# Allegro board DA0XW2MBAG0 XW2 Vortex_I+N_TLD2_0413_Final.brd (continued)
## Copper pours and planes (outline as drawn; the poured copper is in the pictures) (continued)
+SMDDR_VREF_CHB_DIMM_R on BOTTOM (solid shape): 156.67,24.83 156.67,24.55 157,24.22 157,23.64 156.88,23.51 155.94,23.51 155.63,23.81 155.3,23.81 155.23,23.89 155.23,25.29 155.3,25.36 156.15,25.36
+TBT_SVR_IND on BOTTOM (solid shape): outline of 279 points within 349.54,112.23 356.27,117.64
+VAC on TOP (solid shape): 349.54,144.77 349.54,142.92 350.15,142.31 350.15,140.32 349.89,140.07 347.48,140.07 347.22,140.32 347.22,144.26 347.35,144.39 347.99,144.39 348.62,145.02 349.28,145.02
+VAC on BOTTOM (solid shape): outline of 356 points within 343.57,139.79 359.24,148.15
+VAC on IN1 (solid shape): outline of 554 points within 346.84,112.8 350.36,120.87
+VAC on IN3 (solid shape): outline of 187 points within 347.25,41.59 352.58,44.92
+VREFCA_CHA_DIMM on BOTTOM (solid shape): 138.62,27.67 138.82,27.47 138.82,26.58 138.75,26.51 134.35,26.51 134.25,26.54 134.14,26.54 133.87,26.54 133.77,26.63 133.66,26.63 133.61,26.68 133.61,27.5 133.76,27.65 138.27,27.65 138.31,27.68 138.61,27.68
+VREFCA_CHB_DIMM on BOTTOM (solid shape): 155.28,27.5 155.28,27.07 155.78,26.56 155.78,25.72 155.69,25.62 155.12,25.62 155.1,25.62 154.9,25.41 154.9,23.33 154.64,23.08 150.83,23.08 150.72,23.2 150.7,23.2 150.7,23.92 150.81,24.02 153.6,24.02 154.08,24.5 154.08,26.08 154.57,26.56 154.57,27.65 154.62,27.7 155.07,27.7
BATT+ on BOTTOM (solid shape): 212.24,5.78 212.37,5.78 212.39,5.76 213.99,5.76 214.01,5.78 214.33,5.78 214.34,5.76 215.95,5.76 215.96,5.78 216.31,5.78 216.33,5.76 217.93,5.76 217.94,5.78 218.7,5.78 218.82,5.66 218.82,5.39 218.17,4.73 218.17,3.67 217.58,3.09 217.58,2.08 217.57,2.05 217.53,2.03 213.32,2.03 213.28,2.05 213.27,2.08 213.27,3.16 211.5,4.93 211.49,4.93 211.36,5.06 211.36,5.86 211.5,6 212.02,6
BQPHASE on BOTTOM (solid shape): 241.6,25.89 241.6,24.86 241.92,24.55 243.41,24.55 243.64,24.33 243.64,21.2 243.36,20.92 236,20.92 235.62,20.54 235.62,20.21 235.63,20.2 235.63,19.56 235.9,19.29 236.58,19.29 236.68,19.19 236.68,18.4 236.63,18.35 235.77,18.35 235.59,18.18 235.59,15.92 235.34,15.66 229.51,15.66 229,16.17 229,21.2 229.71,21.91 232.29,21.91 236.4,26.02 241.47,26.02
BQVCC on BOTTOM (solid shape): 250,15.8 250,14.96 249.23,14.19 247.74,14.19 247.67,14.26 247.67,14.99 247.99,15.3 248,15.3 248.21,15.42 248.32,15.62 248.32,15.64 248.64,15.95 249.85,15.95
CORE_PLLVDD on TOP (solid shape): 209.21,105.12 209.58,105.12 209.71,104.99 209.71,104.48 209.46,104.23 209.46,104.2 209.45,104.2 209.45,103.59 209.32,103.46 206.66,103.46 206.16,103.96 206.16,105 206.29,105.13 209.2,105.13
CORE_PLLVDD on BOTTOM (solid shape): 232.25,126.34 232.25,122.07 232.67,121.65 232.67,121.63 232.97,121.34 233,121.31 233.04,121.28 233.21,121.11 233.21,120.41 233.09,120.29 230.88,120.29 230.37,120.8 230.37,126.17 230.82,126.62 231.96,126.62
CORE_PLLVDD on IN1 (solid shape): outline of 975 points within 206.14,103.34 221.87,119.98
CTRL_1P0 on BOTTOM (solid shape): 20.26,125.44 20.43,125.37 20.61,125.39 20.64,125.39 20.67,125.38 21.62,124.42 22.29,124.42 22.33,124.41 22.34,124.37 22.34,124.34 23.34,124.34 23.35,124.35 23.4,124.3 23.4,124.19 23.39,124.16 23.35,124.14 22.34,124.14 22.34,124.11 22.33,124.07 22.29,124.06 22.23,124.06 22.21,124.04 21.75,124.04 21.73,124.03 21.71,124.02 21.7,124.02 21.36,123.92 21.26,123.59 21.26,123.56 21.25,123.54 21.11,123.41 17.69,123.41 17.43,123.66 17.43,125.19 17.69,125.44
FBA_VREFC on TOP (solid shape): 228.11,144.12 228.11,140.55 227.93,140.37 227.56,140.37 227.37,140.55 227.37,141.85 227.21,142.02 226.76,142.02 226.58,142.2 226.58,142.61 226.7,142.73 227.01,142.73 227.42,143.14 227.42,144.05 227.57,144.2 228.03,144.2
FBVDDQ_MEM on TOP (solid shape): 228.22,142.16 228.29,142.25 228.4,142.23 228.46,142.17 228.75,142.17 228.88,142.04 228.88,141.97 229.22,141.63 229.23,141.61 229.41,141.38 229.71,141.36 230.03,141.36 230.16,141.23 230.16,140.88 229.97,140.69 229.34,140.69 229,141.03 228.93,141.03 228.9,141.04 228.81,141.18 228.68,141.23 228.4,141.23 228.35,141.22 228.26,141.24 228.22,141.32
FBVDDQ_MEM on TOP (solid shape): outline of 28355 points within 193.5,95.65 253.5,151.88
FBVDDQ_MEM on BOTTOM (solid shape): 225.78,141.42 225.78,141.29 225.66,141.16 225.48,141.16 224.56,142.08 224.56,142.2 224.72,142.36 224.84,142.36
FBVDDQ_MEM on BOTTOM (solid shape): 251.38,110.21 251.38,109.94 250.59,109.15 250.47,109.15 250.36,109.26 250.36,110.16 250.57,110.38 251.21,110.38
FBVDDQ_MEM on BOTTOM (solid shape): 204.09,141.54 204.13,141.5 204.18,141.46 205.4,140.24 205.4,140.05 205.27,139.93 205.12,139.93 203.78,141.27 203.78,141.44 203.94,141.6 204.04,141.6
FBVDDQ_MEM on BOTTOM (solid shape): 243.43,108.74 243.52,108.65 243.62,108.6 244.34,107.88 244.34,107.7 244.19,107.55 244.01,107.55 243.13,108.44 243.13,108.61 243.25,108.74
FBVDDQ_MEM on BOTTOM (solid shape): 224.31,141.29 224.36,141.29 224.86,140.79 224.92,140.71 225,140.64 225,140.48 224.87,140.35 224.69,140.35 223.89,141.16 223.85,141.21 223.8,141.26 223.8,141.42 223.92,141.53 224.07,141.53
FBVDDQ_MEM on BOTTOM (solid shape): 243.39,107.21 243.45,107.08 243.56,106.98 243.56,106.91 243.38,106.74 243.2,106.74 242.46,107.48 242.42,107.55 242.36,107.61 242.36,107.78 242.52,107.93 242.67,107.93
FBVDDQ_MEM on BOTTOM (solid shape): 243.51,110.14 243.73,110.14 243.84,110.04 243.84,109.45 243.67,109.29 243.61,109.28 243.12,109.28 242.95,109.32 242.78,109.28 242.34,109.28 242.34,109.94 242.55,110.15 243.51,110.15
FBVDDQ_MEM on BOTTOM (solid shape): 198.63,141.34 198.63,141.24 197.93,140.54 197.73,140.44 197.63,140.24 197.23,139.84 197.08,139.84 197,139.92 196.98,139.95 196.93,140 196.93,140.23 197.18,140.48 197.22,140.48 198.28,141.54 198.43,141.54
FBVDDQ_MEM on BOTTOM (solid shape): 204.9,142.33 205.02,142.23 205.16,142.2 205.32,142.04 205.38,141.95 205.47,141.89 205.69,141.67 207.25,141.67 207.31,141.67 207.37,141.67 207.47,141.67 207.67,141.47 207.67,141.16 207.54,141.04 207.06,141.04 206.91,141.19 205.38,141.19 204.72,141.85 204.67,141.95 204.6,142.03 204.6,142.2 204.72,142.33
FBVDDQ_MEM on BOTTOM (solid shape): 247.9,130.77 247.9,129.6 247.57,129.27 247.57,128.28 247.75,128.1 247.75,127.69 247.62,127.57 247.34,127.57 247.19,127.72 247.12,127.72 247.1,127.73 246.83,127.76 246.62,127.59 246.53,127.54 246.44,127.59 246.36,127.69 246.25,127.75 246.24,127.75 245.87,128.12 245.87,128.99 245.59,129.27 245.59,130.79 245.64,130.84 247.82,130.84
FBVDDQ_MEM on BOTTOM (solid shape): 216.06,141.57 216.07,141.57 216.14,141.49 216.23,141.43 216.24,141.42 216.26,141.4 216.26,141.35 216.25,141.32 216.23,141.3 216,140.97 216.23,140.64 216.25,140.62 216.26,140.59 216.26,140.53 216.08,140.35 215.55,140.35 215.53,140.36 215.41,140.36 215.17,140.6 215.17,141.93 215.27,142.03 215.6,142.03
FBVDDQ_MEM on BOTTOM (solid shape): 240.96,126.53 241.03,126.39 241.14,126.28 241.14,126.14 240.92,125.92 240.92,125.81 240.98,125.75 241.08,125.56 241.26,125.47 241.78,124.95 241.83,124.82 241.93,124.72 241.93,124.59 241.78,124.44 241.58,124.44 240.85,125.17 240.78,125.27 240.68,125.34 240.28,125.74 240.28,125.97 240.43,126.12 240.43,126.37 240.26,126.55 240.26,126.68 240.48,126.91 240.59,126.91
FBVDDQ_MEM on BOTTOM (solid shape): 223.88,140.2 223.88,140.1 223.65,139.87 223.65,139.58 224.1,139.13 224.3,139 224.54,139.03 224.56,139.03 224.67,139.13 224.82,139.13 224.95,139 224.95,138.55 224.87,138.47 224.62,138.47 224.46,138.32 224.32,138.32 223.39,139.24 223.03,139.24 222.89,139.11 222.89,138.68 223.37,138.21 223.37,138.09 223.12,137.84 222.76,137.84 222.56,138.04 222.56,140.07 222.7,140.21 222.83,140.21 222.84,140.22 223.24,140.22 223.34,140.32 223.38,140.35 223.41,140.39 223.47,140.45 223.63,140.45
FBVDDQ_MEM on BOTTOM (solid shape): 243.52,101.41 243.55,101.33 243.51,101.26 243.5,101.25 243.42,101.17 243.37,101.07 243.37,101.06 242.76,100.45 242.7,100.41 242.65,100.35 242.63,100.34 242.61,100.33 242.48,100.33 242.46,100.34 242.44,100.35 242.39,100.4 242.33,100.44 242.29,100.49 242.29,100.59 242.29,100.62 242.31,100.63 242.37,100.68 242.42,100.73 242.45,100.78 242.48,100.85 243.2,101.58 243.35,101.58
FBVDDQ_MEM on BOTTOM (solid shape): 217.76,142.22 217.76,141.91 217.46,141.6 217.39,141.15 217.84,141.24 218.14,141.54 218.47,141.54 218.57,141.44 218.57,141.24 218.51,141.18 218.46,141.1 217.83,140.47 217.75,140.42 217.69,140.35 217.5,140.35 217.46,140.39 217.43,140.43 217.4,140.46 216.59,141.27 216.59,141.44 216.84,141.7 216.84,141.85 216.88,141.89 216.98,141.95 217.04,142.05 217.33,142.33 217.66,142.33
FBVDDQ_MEM on BOTTOM (solid shape): 239.57,99.04 239.57,98.76 239.39,98.58 239.39,98.11 239.52,97.97 239.53,97.97 239.58,97.92 240.2,97.92 240.48,98.2 240.48,98.73 240.79,99.04 241.09,99.04 241.25,98.89 241.25,96.36 241.07,96.18 240.08,96.18 240.04,96.22 238.58,96.22 238.44,96.08 238.44,95.37 237.93,94.86 237.93,94.22 237.92,94.17 237.92,93.69 237.8,93.56 237.27,93.56 237.14,93.69 237.14,97.3 237.88,98.03 237.9,98.03 238.15,98.14 238.25,98.38 238.25,98.4 238.49,98.64 238.51,98.66 238.53,98.66 238.58,98.66 238.64,98.68 238.81,98.68 239.28,99.15 239.46,99.15
FBVDDQ_MEM on BOTTOM (solid shape): 244.32,100.56 244.32,100.45 244.31,100.43 244.3,100.41 244.23,100.33 244.18,100.23 244.18,100.22 243.64,99.69 243.63,99.68 243.56,99.65 243.49,99.6 243.49,99.59 243.42,99.51 243.39,99.48 243.39,99.13 243.52,99 243.52,99 243.52,98.85 243.26,98.59 243.26,98.06 243.14,97.93 242.44,97.93 242.31,98.06 242.31,98.96 242.47,99.12 242.48,99.13 242.5,99.15 242.5,99.28 243.02,99.79 243.08,99.82 243.2,99.91 243.27,100.04 243.28,100.05 243.87,100.65 243.91,100.67 243.97,100.71 243.99,100.72 244.17,100.72
FBVDDQ_MEM on BOTTOM (solid shape): 241.91,102.21 241.91,102.02 241.84,101.94 241.79,101.85 241.78,101.83 241.77,101.76 241.77,101.72 241.75,101.65 241.69,101.62 241.52,101.53 241.45,101.36 241.45,101.34 241.42,101.31 241.4,101.29 241.38,101.29 241.01,101.1 241.07,100.69 241.14,100.62 241.14,100.51 241,100.37 240.92,100.37 240.69,100.6 240.55,100.6 240.26,100.89 240.26,101.02 240.63,101.4 240.64,101.4 240.78,101.49 240.87,101.62 240.87,101.64 241.55,102.32 241.8,102.32
FBVDDQ_MEM on BOTTOM (solid shape): outline of 260 points within 205.95,103.98 222.57,120.87
FBVDDQ_MEM on BOTTOM (solid shape): outline of 574 points within 245.08,95.69 255.29,108.68
FBVDDQ_MEM on BOTTOM (solid shape): outline of 404 points within 245.08,106.25 252.96,125.64
FBVDDQ_MEM on BOTTOM (solid shape): outline of 1473 points within 191.93,125.23 247.55,151.02
FBVDDQ_MEM on IN3 (solid shape): outline of 16488 points within 193.91,97.07 252.86,150.83
FBVDDQ_MEM on IN4 (solid shape): outline of 3922 points within 194.56,137.4 227.84,151.95
FBVDDQ_VIN on TOP (solid shape): 238.92,154.29 238.92,150.66 238.79,150.54 237.32,150.54 236.76,151.09 236.76,153.65 237.5,154.4 238.82,154.4
FBVDDQ_VIN on BOTTOM (solid shape): 239.05,154.24 239.05,150.37 238.92,150.24 238.92,147.19 238.91,147.16 238.9,147.15 238.87,147.14 238.51,147.14 238.3,146.93 238.3,146.61 238.29,146.6 238.28,146.57 238.27,146.54 238.24,146.52 238.22,146.5 238.18,146.5 238.15,146.5 238.12,146.5 238.09,146.52 238.07,146.54 238.05,146.57 238.04,146.6 238.04,146.61 238.04,146.93 237.83,147.14 237.6,147.15 237.59,147.16 237.58,147.19 237.58,150.08 237.54,150.12 238.04,150.12 238.04,150.73 237.8,150.73 237.8,150.12 237.54,150.12 237.54,150.12 237.54,150.73 237.01,151.25 237.01,151.96 236.84,152.14 232.18,152.14 231.98,152.34 231.98,153.27 232.19,153.49 236.74,153.49 237.65,154.4 238.89,154.4
G5719_LX on TOP (solid shape): 200.09,86.16 200.11,86.16 200.26,86.03 200.41,85.98 200.47,85.98 200.49,85.98 200.51,85.97 200.57,85.91 200.57,83.88 201.2,83.24 201.2,81.97 201.07,81.85 199.96,81.85 199.93,81.88 199.93,82.13 199.6,82.46 199.6,83.01 199.3,83.31 199.3,83.33 199.16,83.54 198.93,83.61 198.86,83.61 198.79,83.59 198.7,83.61 198.66,83.69 198.66,84.05 198.68,84.08 198.69,84.08 198.9,84.42 198.69,84.75 198.67,84.77 198.66,84.8 198.66,84.89 198.67,84.92 198.69,84.94 198.89,85.21 198.8,85.53 198.79,85.53 198.77,85.57 198.77,85.83 198.71,85.89 198.7,85.93 198.71,85.96 198.91,86.16
G5719_VIN on TOP (solid shape): 201.2,80.32 201.2,79.05 201.07,78.93 197.52,78.93 197.28,79.17 197.29,79.17 197.29,80.21 197.26,80.23 197.26,80.32 197.39,80.45 198.25,80.45 198.53,80.74 200.79,80.74
IO_VDD on BOTTOM (solid shape): 262.85,10.07 262.85,9.15 262.87,9.12 262.87,9.1 262.87,8.9 262.36,8.4 261.63,8.4 261.58,8.35 261.58,7.36 261.55,7.33 260.79,7.33 260.76,7.36 260.76,9.59 260.84,9.67 261.35,9.67 261.86,10.17 262.74,10.17
L_SPK+ on TOP (solid shape): 219.44,156.75 219.52,156.75 219.53,156.75 219.55,156.74 219.81,156.49 219.83,156.42 219.83,155.56 219.72,155.45 216.3,155.45 216.12,155.63 216.12,156.49 216.39,156.77 219.36,156.77
L_SPK+_R on TOP (solid shape): 217.22,154.99 217.23,154.98 217.23,154.96 217.23,154.26 217.03,154.05 216.65,154.05 215.84,153.24 215.84,153.02 215.52,152.7 214.39,152.7 214.26,152.83 214.26,153.28 214.43,153.44 214.72,153.44 215.01,153.74 215.01,153.87 215.02,153.87 215.02,154.39 215.74,155.12 217.09,155.12
L_SPK+_R on BOTTOM (solid shape): 214.71,154.6 215.35,154.6 216.06,153.89 216.06,152.62 215.81,152.36 214.43,152.36 214.2,152.58 214.2,153.43 213.72,153.91 213.72,155.01 213.77,155.06 214.26,155.06
L_SPK- on TOP (solid shape): 220.63,153.63 220.63,153.25 220.5,153.13 220.31,153.13 219.78,152.6 216.46,152.6 216.32,152.74 216.32,153.5 216.61,153.8 220.47,153.8
L_SPK-_R on TOP (solid shape): 214.06,153.16 214.06,152.69 214.48,152.27 217.21,152.27 217.42,152.05 217.42,151.32 217.35,151.24 213.48,151.24 213.2,151.52 213.2,153.21 213.39,153.4 213.82,153.4
L_SPK-_R on BOTTOM (solid shape): 213.42,155.03 213.42,153.96 214.03,153.35 214.03,152.62 214.28,152.36 214.28,151.6 213.9,151.22 213.27,151.22 213.14,151.35 213.14,153.18 212.91,153.41 212.91,155.06 212.93,155.08 213.37,155.08
NB679A_SW on BOTTOM (solid shape): 199.21,38.44 199.88,38.44 199.93,38.39 199.93,38.29 199.85,38.22 199.55,38.22 199.37,38.04 199.37,37.61 199.24,37.48 198.46,37.48 197.82,36.84 197.06,36.84 196.63,36.41 196.63,35.4 196.5,35.27 193.07,35.27 192.79,35.55 192.79,38.09 193.15,38.44 198.5,38.44
NB680A_BST on BOTTOM (solid shape): 220.02,43.35 220.02,42.38 219.92,42.28 219.56,42.28 219.44,42.41 219.44,42.86 219.31,42.99 219.03,42.99 218.93,43.09 218.93,43.47 218.98,43.52 219.84,43.52
NB680A_SW on BOTTOM (solid shape): 227.74,44.92 227.74,42.36 227.31,41.92 223.48,41.92 221.91,43.49 220.36,43.49 220.05,43.8 218.19,43.8 218.16,43.82 218.14,43.86 218.14,44.01 218.22,44.08 219.03,44.08 219.08,44.13 219.08,44.49 219.89,45.3 227.36,45.3
NB681BST_1.8 on TOP (solid shape): 294.32,17.01 294.32,16.93 294.31,16.93 294.31,16.35 294.24,16.27 294.11,16.27 294.04,16.35 294.04,16.68 293.5,17.21 292.49,17.21 292.46,17.24 292.46,18.05 292.59,18.18 293.15,18.18
NB681BST_2.5 on BOTTOM (solid shape): 205.12,30.08 205.12,29.67 205.52,29.27 206.03,29.27 206.15,29.14 206.15,29.01 206.03,28.89 205.14,28.89 204.63,29.4 203.52,29.4 203.36,29.56 203.36,30.03 203.65,30.32 204.88,30.32
NB681BST_S_1.8 on TOP (solid shape): 292.21,19.19 292.21,17.44 292.01,17.24 291.24,17.24 291.12,17.36 291.12,19.32 291.24,19.45 291.95,19.45
NB681SW_1.8 on TOP (solid shape): 298.36,20.41 298.36,17.87 298.02,17.54 297.8,17.54 297.53,17.27 295.28,17.27 295.05,17.04 294.95,17.04 294.95,17.02 294.93,16.98 294.9,16.97 294.88,16.97 294.88,16.96 294.85,16.93 294.81,16.93 294.81,16.22 294.82,16.22 294.86,16.2 294.88,16.17 294.88,15.51 294.75,15.38 294.62,15.38 294.53,15.47 294.52,15.51 294.53,15.54 294.56,15.57 294.56,16.22 294.56,16.22 294.56,16.93 294.56,16.93 294.56,17.22 294.37,17.41 294.11,17.41 293.73,17.79 293.73,18.3 293.48,18.56 292.72,18.56 292.34,18.94 292.34,19.45 291.95,19.83 291.32,19.83 291.07,20.08 291.07,20.66 291.19,20.79 297.97,20.79
NB681SW_2.5 on BOTTOM (solid shape): 201.76,33.19 201.76,30.52 201.96,30.32 202.85,30.32 202.98,30.19 202.98,29.43 203.26,29.14 204.38,29.14 204.88,28.63 207.05,28.63 207.11,28.56 207.11,28.45 207.04,28.38 205.39,28.38 204.5,27.49 199.89,27.49 199.36,28.03 199.36,33.43 199.52,33.59 201.35,33.59
NB685BST on TOP (solid shape): 102.61,62.92 102.79,62.92 103.05,62.65 103.05,61.89 102.85,61.69 98.46,61.69 98.33,61.81 98.33,62.7 98.46,62.83 98.71,62.83 98.84,62.7 98.84,62.19 98.93,62.1 98.93,62.1 98.97,62.07 100.11,62.07 101,62.96 102.58,62.96
NB685SW on TOP (solid shape): 98.03,63.97 98.06,63.96 98.08,63.92 98.08,62.5 98.08,61.79 98.08,61.69 98.33,61.43 102.95,61.43 103.05,61.33 103.05,57.65 102.39,56.99 97.44,56.99 96.93,57.49 96.93,61.43 97.7,62.19 97.7,63.92 97.71,63.96 97.75,63.97
NVVDD on TOP (solid shape): 210.31,117.25 210.34,117.21 210.4,117.17 210.42,117.13 210.42,116.84 210.27,116.68 209.94,116.68 209.73,116.47 209.72,116.47 209.69,116.44 209.69,116.03 209.64,115.98 208.98,115.98 208.82,116.14 208.82,117.15 208.95,117.28 210.29,117.28
NVVDD on TOP (solid shape): 217.42,113.45 217.42,109.02 217.3,108.9 212.83,108.9 212.69,109.04 212.69,109.85 212.46,110.08 211.71,110.08 211.64,110.16 211.64,110.8 211.61,110.8 211.49,110.93 210.98,110.93 210.73,111.18 210.73,111.31 210.34,111.69 210.09,111.69 209.84,111.95 209.84,112.2 209.96,112.33 210.22,112.33 210.47,112.07 210.85,112.07 211.49,112.71 212.26,112.71 212.58,112.38 212.58,111.95 212.78,111.75 214.28,111.75 214.46,111.57 214.46,111.3 214.94,110.83 215.4,110.83 215.68,111.11 215.68,111.3 215.81,111.42 216.19,111.42 216.2,111.42 216.41,111.42 216.41,113.01 216.82,113.42 216.91,113.42 217.07,113.58 217.28,113.58
NVVDD on TOP (solid shape): 210.05,109.92 210.06,109.91 210.06,109.89 210.06,106.59 209.92,106.45 209.34,106.45 208.77,107.02 208.77,107.54 209.07,107.84 209.1,107.84 209.44,108.03 209.41,108.42 209.4,108.43 208.87,108.96 208.87,109.04 208.89,109.07 208.88,109.16 208.89,109.47 209.12,109.71 209.12,109.71 209.36,109.8 209.49,110.02 209.49,110.02 209.52,110.05 209.92,110.05
NVVDD on TOP (solid shape): outline of 174 points within 191.9,72.01 218.09,109.29
NVVDD on TOP (solid shape): outline of 230 points within 211.72,106.91 219.62,117.28
NVVDD on BOTTOM (solid shape): outline of 1706 points within 190.18,72.2 221.45,118.59
NVVDD on IN1 (solid shape): outline of 2086 points within 208.68,99.44 219.23,118.24
NVVDD on VCC (solid shape): outline of 18521 points within 176.18,71.72 220.76,118.24
NVVDD on IN2 (solid shape): outline of 4744 points within 191.68,72.06 220.76,118.3
NVVDD on IN3 (solid shape): outline of 2128 points within 208.82,98.9 220.76,117.79
NVVDD_VIN on TOP (solid shape): outline of 877 points within 191.29,55.05 227.31,62.96
NVVDD_VIN on BOTTOM (solid shape): outline of 161 points within 189.14,54.07 229.52,62.44
OPC_BST on BOTTOM (solid shape): 184.44,149.28 183.3,148.13 182.61,148.13 182.53,148.21 182.53,148.93 182.66,149.06 183.57,149.06 184.26,149.74 184.44,149.74
OPC_SW on BOTTOM (solid shape): 184.94,149.28 185.49,148.73 187.43,148.73 187.61,148.55 187.61,145.51 187.36,145.25 181.39,145.25 181.13,145.51 181.13,146.39 181.26,146.52 182.28,146.52 182.53,146.78 182.53,147.66 182.77,147.9 183.31,147.9 184.69,149.28 184.69,150.79 184.94,150.79
OPC_VIN on BOTTOM (solid shape): 184.26,159.97 184.29,159.95 184.31,159.92 184.31,159.26 184.3,159.22 184.26,159.21 183.94,158.84 184.26,158.47 184.3,158.46 184.31,158.42 184.31,154.78 184.82,154.27 184.82,151.36 184.44,150.99 184.44,150.44 184.43,150.4 184.39,150.39 184.24,150.39 184.2,150.4 184.19,150.44 184.19,152.49 182.15,154.53 182.15,156.27 182.16,156.3 182.17,156.31 182.26,156.56 182.16,156.81 182.15,156.82 182.15,156.92 182.16,156.94 182.26,157.17 182.19,157.41 182.18,157.44 182.19,157.48 182.26,157.61 182.26,157.76 182.18,158.06 181.91,158.19 181.87,158.19 181.79,158.19 181.77,158.2 181.26,158.71 181.26,159.92 181.28,159.95 181.31,159.97
OUT_L_A on TOP (solid shape): 222.62,155.3 222.62,154.3 222.33,154.01 219.01,154.01 218.88,154.15 218.88,154.96 218.89,154.98 218.9,154.99 219.06,155.16 221.05,155.16 221.46,155.56 222.36,155.56
OUT_L_A on BOTTOM (solid shape): 222.08,156.39 222.1,156.38 222.11,156.37 222.15,156.34 222.15,155.81 222.21,155.76 222.21,155.75 222.26,155.69 222.32,155.64 222.32,155.64 222.54,155.43 222.54,155.21 222.36,155.03 221.49,155.03 221.38,155.14 221.38,155.48 221.49,155.58 221.65,155.58 221.71,155.64 221.72,155.64 221.85,155.83 221.75,156.03 221.69,156.09 221.57,156.09 221.49,156.18 221.49,156.31 221.56,156.39
OUT_L_B on TOP (solid shape): 221.04,152.49 221.04,151.56 220.75,151.27 218.99,151.27 218.87,151.39 218.87,152.06 219.06,152.25 219.78,152.25 220.35,152.83 220.7,152.83
OUT_L_B on BOTTOM (solid shape): 220.88,156.4 220.9,156.4 220.92,156.39 220.98,156.33 220.99,156.31 220.99,156.2 220.98,156.18 220.88,156.08 220.72,156.08 220.55,155.91 220.55,153.31 220.66,153.2 220.66,151.75 220.46,151.55 219.83,151.55 219.73,151.66 219.73,155.66 220.3,156.22 220.31,156.22 220.49,156.4
OUT_R_A on TOP (solid shape): 203.61,156.17 203.61,155.28 203.49,155.16 202.85,155.16 201.93,154.24 201.11,154.24 200.85,154.51 200.85,155.19 201.33,155.67 201.84,155.67 202.54,156.37 203.42,156.37
OUT_R_A on BOTTOM (solid shape): 201.82,155.44 201.82,154.38 201.65,154.22 200.85,154.22 200.73,154.09 200.73,153.91 200.71,153.88 200.67,153.86 200.54,153.86 200.51,153.88 200.49,153.91 200.49,154.45 200.55,154.51 201.08,154.51 201.22,154.64 201.22,155.44 201.34,155.57 201.7,155.57
OUT_R_B on TOP (solid shape): 203.61,154.65 203.61,153.76 202.9,153.05 202.9,152.72 202.61,152.43 202.6,152.43 202.52,152.39 202.45,152.34 202.43,152.33 202.41,152.32 201.58,152.32 201.47,152.43 201.47,153.1 201.74,153.37 201.74,153.76 202.69,154.71 203.55,154.71
OUT_R_B on BOTTOM (solid shape): 200.65,153.3 200.68,153.28 200.7,153.25 200.7,153.05 200.81,152.94 200.9,152.94 200.91,152.94 200.98,152.92 201.06,152.94 201.07,152.94 202.53,152.94 202.54,152.94 203.29,152.94 203.49,152.74 203.49,152.49 203.36,152.36 202.89,152.36 202.71,152.42 202.52,152.37 202.51,152.36 202.47,152.36 202.42,152.31 202.38,152.24 201.45,152.24 201.44,152.25 201.31,152.39 201.14,152.44 201,152.42 200.88,152.34 200.81,152.31 200.74,152.34 200.68,152.38 200.62,152.41 200.55,152.43 200.45,152.45 200.41,152.48 200.41,153.15 200.41,153.21 200.42,153.23 200.49,153.3
PEX_PLL_HVDD on TOP (solid shape): 207.62,107.86 207.62,107.29 207.04,106.71 207.04,106.23 206.92,106.1 206.21,106.1 206.12,106.15 206.11,106.24 206.03,106.62 205.66,106.71 205.56,106.72 205.52,106.8 205.52,107.44 205.64,107.44 205.78,107.58 206.74,107.58 207.04,107.88 207.6,107.88
PEX_VDD on TOP (solid shape): outline of 225 points within 204.64,113.49 207.69,120.92
PEX_VDD on TOP (solid shape): outline of 1115 points within 201.11,88.21 210.6,105.85
PEX_VDD on BOTTOM (solid shape): outline of 89 points within 205.11,113.24 207.1,118.07
PEX_VDD on IN3 (solid shape): outline of 3637 points within 199.93,91.75 210.47,119.18
PEX_VDD_S on TOP (solid shape): 202.21,92.87 202.21,89 202.37,88.83 203.49,88.83 204.25,88.07 204.25,87.49 204.23,87.45 204.2,87.44 203.69,87.44 203.69,87.43 202.47,87.43 202.39,87.35 202.33,87.35 202.33,86.44 202.34,86.44 202.34,85.28 202.47,85.15 202.85,85.15 202.98,85.02 202.98,84.37 202.96,84.33 202.93,84.32 202.65,84.17 202.58,83.87 202.58,83.84 202.57,83.82 202.5,83.75 201.2,83.75 200.82,84.13 200.82,88.19 200.82,88.21 200.84,88.23 200.94,88.7 200.49,88.87 200.44,88.85 200.41,88.86 200.31,88.96 200.31,89.2 200.33,89.23 200.34,89.23 200.55,89.57 200.34,89.9 200.32,89.92 200.31,89.95 200.31,90.26 199.93,90.64 199.93,92.67 200.15,92.9 202.18,92.9
PS8331_1P5V_3V on TOP (solid shape): 66.96,70.45 66.96,70.07 67.22,69.81 67.22,69.31 67,69.09 66.67,69.09 66.63,69.13 66.63,69.76 66.2,70.19 66.2,70.45 66.33,70.58 66.83,70.58
PS8331_CEXT_1P5V on TOP (solid shape): 60.66,62.24 62.03,62.24 62.03,62.23 62.83,62.23 62.87,62.19 62.87,62.07 62.85,62.04 61.6,62.04 60.97,61.41 57.94,61.41 57.87,61.48 57.87,62.32 57.91,62.37 60.54,62.37
PVADPTR on TOP (solid shape): outline of 4580 points within 302.67,19.08 338.36,148.05
PVADPTR on BOTTOM (solid shape): 331.5,145.38 331.5,139.28 331.25,139.03 330.11,139.03 329.85,139.28 329.85,145.25 330.11,145.51 331.38,145.51
PVADPTR on BOTTOM (solid shape): 256.55,22.34 256.55,20.82 256.52,20.79 252.76,20.79 252.44,21.11 252.44,21.12 252.19,21.37 252.19,23.52 252.71,24.04 254.84,24.04
PVADPTR on GND (solid shape): outline of 1274 points within 327.02,85.05 337.6,143.98
PVADPTR on IN1 (solid shape): outline of 1324 points within 327.72,84.55 338.13,143.98
PVADPTR on IN4 (solid shape): outline of 5813 points within 253.14,2.33 313.85,23.85
R_SPK+ on TOP (solid shape): 205.7,156.37 207.58,156.37 207.77,156.18 207.77,155.48 207.51,155.21 204.15,155.21 204.03,155.34 204.03,156.97 204.12,157.06 205.01,157.06
R_SPK+_R on TOP (solid shape): 211.06,155.46 211.06,153.7 211.24,153.52 211.43,153.51 211.48,153.51 211.72,153.27 211.72,152.82 211.59,152.69 210.2,152.69 209.71,153.18 209.71,154.78 209.33,155.16 208.44,155.16 208.19,155.41 208.19,156.3 208.44,156.55 209.96,156.55
R_SPK+_R on BOTTOM (solid shape): 211.82,154.98 211.82,152.69 211.61,152.49 210.09,152.49 209.96,152.62 209.96,154.01 211,155.06 211.74,155.06
R_SPK- on TOP (solid shape): 207.73,154.71 207.73,153.93 207.57,153.77 204.22,153.77 204.07,153.92 204.07,154.75 204.34,155.02 207.42,155.02
R_SPK-_R on TOP (solid shape): 209.46,154.52 209.46,153 210.15,152.3 211.63,152.3 211.96,152.62 211.96,153.28 212.09,153.41 212.53,153.41 212.87,153.07 212.87,151.38 212.66,151.18 209.12,151.18 208.07,152.23 208.07,154.59 208.19,154.7 209.27,154.7
R_SPK-_R on BOTTOM (solid shape): 212.6,155.01 212.6,153.41 212.88,153.13 212.88,151.35 212.76,151.22 211.74,151.22 211.61,151.35 211.61,152.24 212,152.62 212,153.96 212.1,154.07 212.1,155.03 212.12,155.06 212.55,155.06
RTS5237_AV12 on BOTTOM (solid shape): 28.25,66.18 28.25,64.71 28.1,64.56 26.47,64.56 26.4,64.63 26.4,65.46 26.4,65.47 26.44,65.62 26.4,65.78 26.4,65.79 26.4,65.85 26.85,66.31 28.12,66.31
TBTA_CC1 on BOTTOM (solid shape): 360.43,125.34 360.43,124.65 360.33,124.55 358.92,124.55 358.88,124.56 358.87,124.59 358.75,124.8 358.53,124.87 358.46,124.9 358.43,124.97 358.43,125.31 358.55,125.44 360.33,125.44
TBTA_CC2 on TOP (solid shape): 361.4,131.45 361.44,131.45 361.55,131.33 362.41,131.33 362.44,131.31 362.44,131.1 362.42,131.08 361.55,131.08 361.55,131.08 361.02,131.08 360.99,131.08 360.88,131.2 359.86,131.2 359.75,131.31 359.75,131.56 359.83,131.64 361.21,131.64
TBTA_VBUS_L on TOP (solid shape): 346.49,138.88 346.49,136.62 346.2,136.32 344.02,136.32 344.02,136.33 343.83,136.33 343.26,136.9 343.03,136.9 342.93,137 342.93,138.65 343.06,138.77 345.75,138.77 345.9,138.93 346.44,138.93
TBTA_VBUS_L on TOP (solid shape): 357.29,128.87 357.56,128.75 357.86,128.7 358.46,128.7 358.55,128.61 358.55,127.22 358.59,127.18 358.67,127.06 358.79,126.98 359.06,126.71 359.06,126.58 358.93,126.46 356.52,126.46 356.14,126.84 356.14,128.74 356.27,128.87
TBTA_VBUS_L on TOP (solid shape): 366.08,133.47 366.08,130.42 365.42,129.76 364.4,129.76 364.27,129.88 364.27,130.39 364.25,130.41 364.25,130.44 364.22,130.44 364.14,130.52 364.14,130.58 363.26,130.58 363.23,130.62 363.23,130.8 363.25,130.82 364.98,130.82 365.13,130.98 365.13,132.42 364.47,133.09 363.84,133.09 363.81,133.09 363.29,133.09 363.25,133.14 363.25,133.31 363.27,133.34 364.14,133.34 364.14,133.34 364.22,133.34 364.62,133.75 365.8,133.75
TBTA_VBUS_L on TOP (solid shape): 356.14,141.03 356.14,141.01 356.16,140.86 356.21,140.72 356.28,140.6 356.37,140.5 356.38,140.49 356.39,140.45 356.64,140.21 357.18,140.21 357.38,140 357.38,139.38 357.23,139.22 356.99,139.22 356.97,139.23 356.95,139.24 356.65,139.4 356.35,139.24 356.33,139.23 356.31,139.22 353.74,139.22 353.5,139.46 353.5,139.67 353.39,139.78 353.36,139.78 353.35,139.79 353.3,139.79 353.23,139.82 353.2,139.9 353.18,140.04 353.08,140.14 352.97,140.17 352.86,140.15 352.76,140.15 352.71,140.24 352.71,140.43 352.84,140.55 353.73,140.55 354.24,141.06 356.11,141.06
TBTA_VBUS_L on BOTTOM (solid shape): outline of 162 points within 360.23,129.76 365.21,134.58
TBTA_VBUS_L on IN1 (solid shape): outline of 2563 points within 343.69,126.46 365.44,141.09
TBTB_CC1 on TOP (solid shape): 360.33,111.22 360.33,109.95 360.2,109.82 359.19,109.82 359.06,109.95 359.06,110.71 359.7,111.34 360.2,111.34
TBTB_CC2 on TOP (solid shape): 361.4,114.81 361.44,114.81 361.55,114.69 362.41,114.69 362.44,114.67 362.44,114.46 362.42,114.44 361.55,114.44 361.55,114.44 361.01,114.44 360.99,114.44 360.88,114.56 359.86,114.56 359.75,114.67 359.75,114.92 359.83,115 361.21,115
TBTB_CC2 on BOTTOM (solid shape): 359.32,111.34 359.32,110.71 359.19,110.58 358.55,110.58 358.43,110.45 358.43,110.07 358.3,109.95 358.05,109.95 357.54,110.46 357.54,111.34 357.66,111.47 359.19,111.47
TBTB_CC2 on IN2 (solid shape): 361.65,115.08 361.65,114.64 361.5,114.49 359.98,114.49 359.57,114.9 359.57,115.28 359.82,115.53 361.19,115.53
TBTB_VBUS_L on TOP (solid shape): 366.08,116.82 366.08,113.78 365.42,113.12 364.4,113.12 364.25,113.27 364.25,113.8 364.22,113.8 364.14,113.88 364.14,113.94 363.26,113.94 363.23,113.98 363.23,114.16 363.25,114.18 364.98,114.18 365.13,114.34 365.13,115.85 364.65,116.33 364.59,116.33 364.47,116.44 363.84,116.44 363.81,116.45 363.29,116.45 363.25,116.5 363.25,116.67 363.27,116.7 364.14,116.7 364.14,116.7 364.22,116.7 364.83,117.31 365.59,117.31
TBTB_VBUS_L on TOP (solid shape): 345.38,135.1 345.38,132.72 345.5,132.6 345.73,132.6 345.8,132.53 345.8,132.32 345.7,132.22 343.3,132.22 343.3,132.45 343.23,132.6 343.08,132.66 342.8,132.66 342.77,132.66 342.69,132.68 342.65,132.76 342.65,133.14 342.93,133.42 342.93,134.96 343.06,135.09 343.69,135.09 343.77,135.17 345.32,135.17
TBTB_VBUS_L on BOTTOM (solid shape): outline of 183 points within 359.83,113.12 365.22,117.95
TBTB_VBUS_L on IN3 (solid shape): outline of 2801 points within 342.65,112.74 366.17,134.46
TYPEC1_USB0 on TOP (solid shape): 342.55,139.79 342.55,136.87 342.44,136.76 336.66,136.76 336.58,136.83 336.58,139.79 336.96,140.17 337,140.17 337.07,140.14 337.1,140.06 337.31,139.71 337.72,139.77 337.79,139.8 337.86,139.77 338.11,139.68 338.36,139.78 338.43,139.8 338.49,139.77 338.9,139.71 339.11,140.06 339.14,140.14 339.21,140.17 341.1,140.17 341.36,140.43 341.92,140.43
TYPEC2_USB0 on TOP (solid shape): 338.89,135.9 342.45,135.9 342.55,135.8 342.55,133.31 342.3,133.06 337.57,133.06 337.25,132.74 337.25,132.42 337.09,132.27 336.73,132.27 336.58,132.41 336.58,136.36 336.71,136.49 338.31,136.49
VADPBL on TOP (solid shape): 341.28,147.54 341.28,146.39 341.54,146.14 343.12,146.14 343.43,145.84 343.43,145.53 343.68,145.28 346.62,145.28 346.74,145.15 346.74,140.78 346.62,140.65 336.48,140.65 336.46,140.68 336.46,145.12 336.71,145.38 338.11,145.38 338.74,146.01 338.74,147.54 339,147.79 341.03,147.79
VADPBL on BOTTOM (solid shape): 343.06,145.89 343.06,140.81 342.81,140.55 338.36,140.55 337.98,140.93 337.98,145.25 338.39,145.66 338.39,145.79 338.74,146.14 342.81,146.14
WIFI_3V on BOTTOM (solid shape): 335.57,64.23 335.57,59.65 335.44,59.53 334.96,59.53 334.85,59.63 334.85,60.16 334.73,60.29 334.73,61 334.3,61.43 332.77,61.43 332.52,61.69 332.52,63.08 332.77,63.34 334.55,63.34 334.68,63.46 334.68,64.23 334.8,64.35 335.44,64.35
WIFI_3V on BOTTOM (solid shape): 333.41,78.32 336.07,78.32 336.2,78.2 336.2,77.18 336.46,76.93 336.86,76.93 336.94,76.85 336.94,75.76 336.84,75.66 335.82,75.66 335.57,75.4 335.57,74.69 335.55,74.65 335.52,74.64 334.73,74.64 334.69,74.65 334.68,74.69 334.68,75.4 334.42,75.66 332.16,75.66 331.96,75.86 331.96,78.65 332.14,78.83 332.9,78.83
WIFI_3V on IN1 (solid shape): outline of 522 points within 328.48,62.5 336.33,76.75
N17269856 on BOTTOM (solid shape): 201.94,158.95 201.94,158.48 201.94,158.47 201.91,158.33 201.94,158.2 201.94,158.19 201.94,157.37 200.73,156.17 200.73,156.12 200.7,156.09 200.7,154.66 200.64,154.61 200.52,154.61 200.49,154.64 200.49,156.94 200.44,157 200.44,157.09 199.98,157.54 199.98,158.83 200.26,159.1 201.79,159.1
N17269865 on BOTTOM (solid shape): 203.63,158.97 203.66,158.95 203.68,158.92 203.68,153.51 203.22,153.06 203.21,153.05 203.19,153.04 200.86,153.04 200.82,153.07 200.81,153.09 200.81,153.12 200.81,153.15 200.8,153.23 200.8,153.44 200.8,153.44 200.81,153.55 200.8,153.62 200.8,153.71 200.8,153.72 200.8,153.81 200.83,153.84 200.83,154.04 200.86,154.07 201.73,154.07 201.96,154.3 201.96,155.45 201.67,155.74 201.33,155.74 201.1,155.52 201.1,154.67 201.04,154.61 200.86,154.61 200.8,154.66 200.81,154.76 200.8,154.82 200.81,155.15 200.8,155.22 200.81,155.55 200.8,155.62 200.8,156.02 200.81,156.04 200.82,156.06 200.84,156.08 201.66,156.91 201.69,156.91 201.93,157.01 202.04,157.26 202.04,157.28 202.6,157.85 202.6,158.21 202.6,158.22 202.62,158.33 202.6,158.45 202.6,158.46 202.6,158.92 202.62,158.95 202.65,158.97
N17269924 on BOTTOM (solid shape): 226.98,156.64 226.98,155.05 226.77,154.84 225.02,154.84 223.75,156.11 222.36,156.11 222.3,156.17 222.3,156.31 222.4,156.42 222.46,156.42 222.78,156.42 222.82,156.42 222.86,156.42 223.18,156.42 223.22,156.42 223.26,156.42 225.17,156.42 225.74,156.99 226.62,156.99
N17269924 on BOTTOM (solid shape): 226.98,156.64 226.98,155.05 226.77,154.84 225.02,154.84 223.75,156.11 222.36,156.11 222.3,156.17 222.3,156.31 222.4,156.42 222.46,156.42 222.78,156.42 222.82,156.42 222.86,156.42 223.18,156.42 223.22,156.42 223.26,156.42 225.17,156.42 225.74,156.99 226.62,156.99
N17269933 on BOTTOM (solid shape): 221.62,155.97 221.65,155.96 221.67,155.92 221.67,155.74 221.61,155.69 221.45,155.69 221.43,155.68 221.31,155.56 221.31,155.55 221.28,155.52 221.28,155.41 221.27,155.31 221.28,155.22 221.28,155.09 221.45,154.93 222.4,154.93 222.41,154.94 222.48,154.94 222.63,155.09 222.63,155.16 222.64,155.17 222.64,155.47 222.27,155.84 222.27,155.9 222.33,155.97 223.63,155.97 224.95,154.65 226.35,154.65 226.73,154.27 226.73,153.51 226.6,153.38 221.01,153.38 220.68,153.71 220.68,155.89 220.75,155.96 220.76,155.97 220.78,155.97
N18005245 on BOTTOM (solid shape): 35.74,49.62 35.74,48.25 35.53,48.03 34.03,48.03 34.02,48.02 31.22,48.02 31.05,48.2 31.05,49.44 31.48,49.87 35.49,49.87
N19453152 on BOTTOM (solid shape): 232.67,72.76 233.62,72.76 233.71,72.66 233.91,72.46 233.95,72.43 234.23,72.15 234.26,72.11 234.46,71.91 234.5,71.88 234.78,71.6 234.78,71.53 235.02,71.29 235.02,71.25 236.71,69.56 236.71,69.45 236.25,68.99 236.12,68.99 234.15,70.96 233.84,70.96 232.98,71.81 232.86,71.81 232.85,71.82 232.7,71.85 232.55,71.82 232.54,71.81 232.28,71.81 231.68,72.42 231.68,72.67 232.1,73.09 232.34,73.09
N22855262 on TOP (solid shape): 141.36,145.96 141.36,145.46 141.71,145.1 141.71,144.06 141.61,143.96 140.54,143.96 140.11,144.39 140.11,145.25 140.9,146.04 141.28,146.04
N22855337 on TOP (solid shape): 149.89,145.71 149.89,145.05 149.61,144.77 149.61,144.11 149.31,143.8 148.55,143.8 148.47,143.88 148.47,145.58 148.72,145.84 149.77,145.84
N22855427 on TOP (solid shape): 158.25,145.71 158.25,143.88 158.15,143.78 157.59,143.78 157.44,143.93 157.44,144.59 156.95,145.07 156.95,145.43 157.28,145.76 158.2,145.76
N22855516 on TOP (solid shape): 168.05,145.68 168.05,145.23 167.76,144.93 167.76,144.12 167.42,143.78 166.81,143.78 166.68,143.91 166.68,145.61 166.96,145.89 167.85,145.89
N22857752 on BOTTOM (solid shape): 124.49,118.71 124.49,117.95 124.25,117.71 123.23,117.71 122.97,117.44 122.71,117.44 122.4,117.76 122.4,118.71 122.52,118.84 124.37,118.84
N22857755 on BOTTOM (solid shape): 125.05,126.86 125.05,126.35 124.9,126.2 124.46,126.2 123.62,125.36 123.62,125.16 122.93,125.16 122.93,125.96 123.28,125.96 124.26,126.94 124.97,126.94
N22857779 on BOTTOM (solid shape): 127.54,107.91 127.54,107.15 127.41,107.02 125.76,107.02 125.64,107.15 125.64,107.91 125.76,108.04 127.41,108.04
N22857782 on BOTTOM (solid shape): 125.97,114.85 125.97,114.37 125.89,114.29 125.64,114.29 125.48,114.14 125.35,114.14 124.51,113.3 124.51,113.1 123.81,113.9 124.26,113.9 125.28,114.92 125.89,114.92
N22857845 on BOTTOM (solid shape): 173.67,148.58 173.67,148.05 173.13,147.51 173.13,146.74 173.01,146.62 172.43,146.62 172.32,146.73 172.32,148.33 172.65,148.66 173.59,148.66
N22857847 on BOTTOM (solid shape): 178.36,147.27 179.48,146.15 179.48,145.8 179.41,145.73 178.75,145.73 178.67,145.81 178.67,146.09 178.19,146.57 177.91,146.57 177.56,146.93 177.56,147.63 178.36,147.63
N25796977 on BOTTOM (solid shape): 238.54,146.62 238.67,146.75 238.8,146.62 238.8,146.24 237.65,145.09 237.65,144.46 237.27,144.08 236.38,144.08 236.25,144.2 236.25,144.46 236.63,144.84 236.63,145.42 237.32,146.11 238.33,146.11 238.54,146.32
N32334559 on TOP (solid shape): 343.68,136.12 345.57,136.12 345.67,136.02 345.67,135.38 345.64,135.35 342.93,135.35 342.68,135.6 342.68,136.36 342.81,136.49 343.31,136.49
N32334561 on TOP (solid shape): 344.3,139.82 347.68,139.82 347.76,139.74 347.76,139.23 347.68,139.16 345.9,139.16 345.65,138.9 342.93,138.9 342.81,139.03 342.81,139.92 342.93,140.04 344.08,140.04
N33864385 on TOP (solid shape): 56.14,54.09 56.14,53.31 55.84,53 55.84,51.99 55.73,51.89 54.92,51.89 54.68,51.65 53.5,51.65 53.37,51.78 53.37,54.32 53.5,54.45 55.79,54.45
N33864703 on TOP (solid shape): 48.88,59.15 48.88,57.14 48.77,57.04 47.5,57.04 47.38,57.16 47.38,59.2 47.45,59.27 48.75,59.27
N36026151 on BOTTOM (solid shape): 182.15,148.93 182.15,146.9 182.02,146.78 181.26,146.78 181.13,146.9 181.13,147.49 180.88,147.74 180.63,147.74 180.45,147.92 180.45,148.25 181.26,149.06 182.02,149.06
N36798878 on BOTTOM (solid shape): 245.5,151.49 245.5,150.73 245.37,150.6 243.72,150.6 243.59,150.73 243.59,151.49 243.72,151.62 245.37,151.62
N36799011 on BOTTOM (solid shape): 240.6,144.97 241.21,144.97 241.33,144.84 241.33,144.38 241.26,144.31 239.53,144.31 239.43,144.41 239.43,145.35 239.53,145.45 240.11,145.45
N56147116 on TOP (solid shape): 350.4,22.44 350.4,21.91 350.53,21.78 351.06,21.78 351.09,21.76 351.09,20.41 350.92,20.24 350.91,20.24 350.8,20.16 350.72,20.05 350.72,20.05 350.68,20 350.68,19.73 350.63,19.67 349.46,19.67 349.13,20 349.13,20.92 349.41,21.2 349.41,22.32 349.56,22.47 350.37,22.47

Small or netless copper shapes (teardrops, artwork), in the pictures only: 61 on TOP, 16 on BOTTOM, 5 on IN1, 137 on IN2, 4 on IN3, 4 on IN4

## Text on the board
Ref Des/Silkscreen Bottom: M2.5X6.5 | REV:G | DA0XW2MBAG0 | WWAN
User.Comments: 39.0x94.0 | 39.0x110.0 | 30.0x32.0
Ref Des/Silkscreen Top: DA0XW2MBAG0 | REV:G | MODEL:XW2A
BODY_CENTER: HT& HB
User.7: Vortex 15 MB _180412 | KB Con | KB BL con | Audio jack | RTC | USB Type C | HDMI Con | SD Card | Point stick con | INTEL+NV
User.8: USB3.0 | USB 3.0 | RJ45 | ALS Con | Power button Con | Touch cable Con | Fan con | HDD Con | Touchpad FFC con | Battery | Dream color FFC Con | Fan conn | NFC CONN | Smart card FFC con | LCD Cable Conn | SPK Con | Finger print con | Sim card | DC IN
User.13: GND | +3V | +5VPCU | +5V | +VCC_CORE | +VCC_GT | +1.2VSUS | NVVDD | +3VPCU | +5V_USBSRC | +1.05V_DEEP_SUS | AGND | +VCC_SA | CCG5_VBUS_CSN_P2 | CCG5_VBUS_CSN_P1
User.29: GND | AGND
User.30: GND
User.31: GND
User.45: XY-Outline check:Nov 08 14:27:44 2017 | outline check:Nov 08 14:27:44 2017 | PT_TOP | PT_BOT | FIGURE | TYPE | Oblong | Circle | SIZE | 51.0x31.0 | 55.0x20.0 | 55.0x24.0 | 55.0x39.0 | 59.0x24.0 | 59.0x28.0 | 59.0x30.0 | 59.0x35.0 | 63.0x20.0 | 73.0x31.0 | 79.0x24.0 | 87.0x39.0 | 130.0x118.0 | 157.0x118.0 | 8.0 | 10.0 | 12.0 | 14.0 | 22.0 | 28.0 | 31.0 | 35.0 | 39.0 | 61.0 | 102.0 | 118.0 | 138.0 | 146.0 | 30.0 | 32.0 | 33.0 | 37.0 | 40.0 | 41.0 | 43.0 | 45.0 | 47.0 | 49.0 | 63.0 | 67.0 | DRILL CHART: TOP to BOTTOM | ALL UNITS ARE IN MILS | PLATED | NON-PLATED | ROTATION | 0.000 | 90.000 | - | QTY | 6 | 4 | 2 | 1 | 53 | 488 | 3 | 8159 | 37 | 9 | 1344 | 19 | 22 | 27 | 8 | 12 | 20 | 5 | 10197 | TOTAL HOLES:
